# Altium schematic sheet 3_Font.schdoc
size 431 x 309 mm; Symbol: Sheet-Symbol_A3; Device: Sheet-Symbol_A3; Company: 嘉立创EDA; Version: V1.0; Page Size: A3; @Project Name: 辉光管_2024.2.16; @Page Count: 3; @Update Date: 2024-07-19; @Create Date: 2024-03-15; @Schematic Name: Schematic1; @Page No: 3; @Page Name: Font
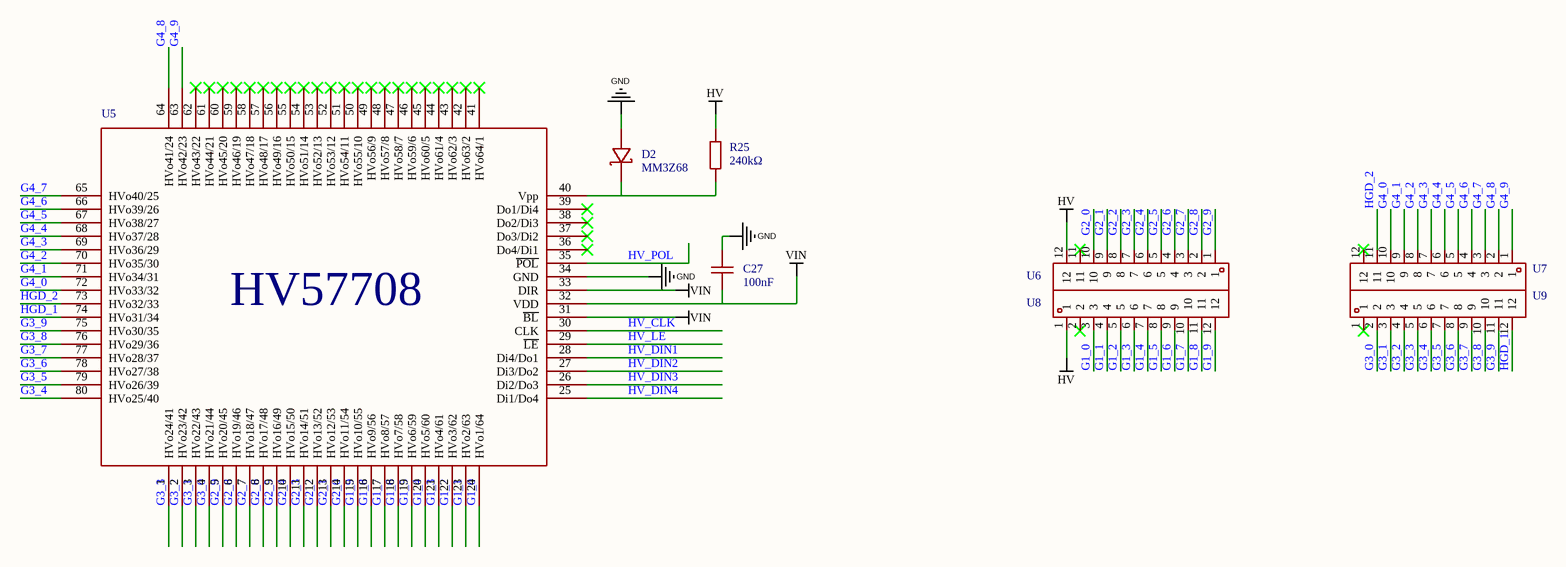
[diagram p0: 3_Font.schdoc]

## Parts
C27  100nF  [C0603]  (value not drawn)
D2  MM3Z68  [SOD-323_L1.8-W1.3-LS2.5-RD-1]  (value not drawn)
R25  240kΩ  [R0805]  (value not drawn)
U5  HV57708  [PQFP-80_L20.0-W14.0-P0.80-LS23.2-BL]  (value not drawn)
U6  KH-2.54FH-1X12P-H8.5  [HDR-TH_12P-P2.54-V-F]  (value not drawn)
U7  KH-2.54FH-1X12P-H8.5  [HDR-TH_12P-P2.54-V-F]  (value not drawn)
U8  KH-2.54FH-1X12P-H8.5  [HDR-TH_12P-P2.54-V-F]  (value not drawn)
U9  KH-2.54FH-1X12P-H8.5  [HDR-TH_12P-P2.54-V-F]  (value not drawn)

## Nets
GND: C27.2 D2.2(A) U5.34(GND)
HV: R25.2 U6.12 U8.1
VIN: C27.1 U5.31(~{BL}) U5.32(VDD) U5.33(DIR)
G1_0: U5.24(HVo1/64) U8.3
G1_1: U5.23(HVo2/63) U8.4
G1_2: U5.22(HVo3/62) U8.5
G1_3: U5.21(HVo4/61) U8.6
G1_4: U5.20(HVo5/60) U8.7
G1_5: U5.19(HVo6/59) U8.8
G1_6: U5.18(HVo7/58) U8.9
G1_7: U5.17(HVo8/57) U8.10
G1_8: U5.16(HVo9/56) U8.11
G1_9: U5.15(HVo10/55) U8.12
G2_0: U5.14(HVo11/54) U6.10
G2_1: U5.13(HVo12/53) U6.9
G2_2: U5.12(HVo13/52) U6.8
G2_3: U5.11(HVo14/51) U6.7
G2_4: U5.10(HVo15/50) U6.6
G2_5: U5.9(HVo16/49) U6.5
G2_6: U5.8(HVo17/48) U6.4
G2_7: U5.7(HVo18/47) U6.3
G2_8: U5.6(HVo19/46) U6.2
G2_9: U5.5(HVo20/45) U6.1
G3_0: U5.4(HVo21/44) U9.2
G3_1: U5.3(HVo22/43) U9.3
G3_2: U5.2(HVo23/42) U9.4
G3_3: U5.1(HVo24/41) U9.5
G3_4: U5.80(HVo25/40) U9.6
G3_5: U5.79(HVo26/39) U9.7
G3_6: U5.78(HVo27/38) U9.8
G3_7: U5.77(HVo28/37) U9.9
G3_8: U5.76(HVo29/36) U9.10
G3_9: U5.75(HVo30/35) U9.11
G4_0: U5.72(HVo33/32) U7.10
G4_1: U5.71(HVo34/31) U7.9
G4_2: U5.70(HVo35/30) U7.8
G4_3: U5.69(HVo36/29) U7.7
G4_4: U5.68(HVo37/28) U7.6
G4_5: U5.67(HVo38/27) U7.5
G4_6: U5.66(HVo39/26) U7.4
G4_7: U5.65(HVo40/25) U7.3
G4_8: U5.64(HVo41/24) U7.2
G4_9: U5.63(HVo42/23) U7.1
HGD_1: U5.74(HVo31/34) U9.12
HGD_2: U5.73(HVo32/33) U7.11
HV_CLK: U5.30(CLK)
HV_DIN1: U5.28(Di4/Do1)
HV_DIN2: U5.27(Di3/Do2)
HV_DIN3: U5.26(Di2/Do3)
HV_DIN4: U5.25(Di1/Do4)
HV_LE: U5.29(~{LE})
HV_POL: U5.35(~{POL})
NetD2_1: D2.1(C) R25.1 U5.40(Vpp)

Not connected (* = marked no-connect by the designer): U5 36(Do4/Di1)* 37(Do3/Di2)* 38(Do2/Di3)* 39(Do1/Di4)* 41(HVo64/1)* 42(HVo63/2)* 43(HVo62/3)* 44(HVo61/4)* 45(HVo60/5)* 46(HVo59/6)* 47(HVo58/7)* 48(HVo57/8)* 49(HVo56/9)* 50(HVo55/10)* 51(HVo54/11)* 52(HVo53/12)* 53(HVo52/13)* 54(HVo51/14)* 55(HVo50/15)* 56(HVo49/16)* 57(HVo48/17)* 58(HVo47/18)* 59(HVo46/19)* 60(HVo45/20)* 61(HVo44/21)* 62(HVo43/22)*; U6 11*; U7 12*; U8 2*; U9 1*

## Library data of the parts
C27 = 0603B104K500NT: 容值:100nF;精度:±10%;额定电压:50V;材质(温度系数):X7R;; Manufacturer: FH(风华); Add into BOM: yes; Tolerance: ±10%; Voltage Rated: 50V; Temperature Coefficient: X7R
D2 = MM3Z68_C118625: 二极管配置:独立式;稳压值(标称值):68V;稳压值(范围):64V~72V;功率:300mW;精度:-;; Manufacturer: ST(先科); Add into BOM: yes; Diode Configuration: 独立式; Zener Voltage (Nom): 68V; Reverse Leakage Current (Ir): 200nA@52V; Power Dissipation: 300mW; Zener Impedance (Zzt): 250Ω
R25 = 0805W8F2403T5E: 电阻类型:厚膜电阻;阻值:240kΩ;精度:±1%;功率:125mW;最大工作电压:150V;温度系数:±100ppm/℃;; Manufacturer: UNI-ROYAL(厚声); Add into BOM: yes; Tolerance: ±1%; Power(Watts): 125mW; Overload Voltage (Max): 150V
U5 = HV57708: Add into BOM: yes
U6-U9 = KH-2.54FH-1X12P-H8.5: 插孔结构:1x12P;间距:2.54mm;行距:-;圆孔/方孔:方孔;安装类型:直插;排数:单排;总孔位数:12P;额定电流:3A;额定电压:-;插孔方向:顶部;塑高:8.5mm;工作温度范围:-40℃~+105℃;; Manufacturer: kinghelm(金航标); Add into BOM: yes; Holes Structure: 1x12P; Pitch: 2.54mm; Circular Hole / Square Hole: 方孔; Number of Holes: 12P; Current Rating (Max): 3A; Holes Direction: 顶部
